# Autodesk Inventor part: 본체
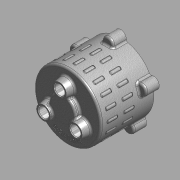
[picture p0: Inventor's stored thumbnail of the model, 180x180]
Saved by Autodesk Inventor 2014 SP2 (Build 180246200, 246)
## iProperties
Created: 2015-11
Part Number: 본체
Document SubType Name: 모델링
Designer: mdu
Material: 알루미늄 6061
Density: 2.71 g/cm^3
Appearance: 알루미늄 - 평지
Mass: 487.643 g
Surface Area: 696.803 cm^2
Volume: 179.942 cm^3
변환 표준: STEP AP214IS
파일 이름: C:\Users\SeoGD\Desktop\?쒗뿕\紐몄껜.stp
전처리기: Build: 253, Release: 2010 SP1 - Date: Wed 07/29/2009
전송 단위: 밀리미터
불확실성: 0.01
Author: mdu
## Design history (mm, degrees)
sketch "스케치2"
  geometry: C1 r 50 at (0, 0); 1 further point
  constraints: 1 centre point, 1 coincident
  dimensions: "d9" = 100 diameter of C1
extrude "돌출2" new body sketch "스케치2" distance "d10" = 80; taper "d11" = 0 deg
feature "쉘1" dims "d12" = 5
sketch "스케치3" dims "d13" = 55
  geometry: C1 r 7.5 at (0, 27.5); C2 r 12.5 at (0, 27.5); 2 further points
  constraints: 2 centre point, 2 coincident, 2 vertical alignment, 2 other
  dimensions: "d14" = 15 diameter of C1; "d15" = 25 diameter of C2
extrude "돌출3" join sketch "스케치3" distance "d16" = 12; taper "d17" = -10 deg
hole "구멍2" diameter "d20" = 15; stored, may be unused: countersink angle "d24" = 90 deg, drill point angle "d26" = 118 deg; dims "d18" = 10, "d19" = 10, "d21" = 6, "d22" = 4, "d23" = 2, "d25" = 15
chamfer "모따기1" distance "d27" = 1; stored, may be unused: second distance "d28" = 2, angle "d29" = 45 deg
sketch "스케치4"
  geometry: L1 (0, 0)-(0, 88); L2 (0, 70)-(13.16, 70); L3 (-45, 75)-(45, 75) reference; L4 (-50, 80)-(50, 80) reference; L5 (13.16, 70)-(14.5, 75); L6 (20, 80)-(20, 88); L7 (20, 88)-(0, 88); L8 (20, 80)-(14.5, 75)
  constraints: 12 end point, 3 point on line, 2 perpendicular, 1 vertical
  dimensions: "d34" = 40 diameter of L6 L1; "d35" = 105 deg angle of L5 L3; "d36" = 5 distance between parallel lines of L2 L3; "d37" = 8 distance between parallel lines of L7 L4; "d51" = 29 diameter of L5.end L1
revolve "회전1" sketch "스케치4" stored, may be unused: angle "d38" = 90 deg
hole "구멍3" diameter "d41" = 15; stored, may be unused: countersink angle "d45" = 90 deg, drill point angle "d47" = 0 deg; dims "d39" = 10, "d40" = 10, "d42" = 6, "d43" = 22, "d44" = 13, "d46" = 15
chamfer "모따기2" distance "d48" = 1; stored, may be unused: second distance "d49" = 2, angle "d50" = 45 deg
fillet "모깎기1" dims "d52" = 3
fillet "모깎기2" dims "d53" = 3, "d72" = 0.2
sketch "스케치5"
  geometry: A1 r 50 centre (0, 0) between (50, 0) and (-8.074, 49.344) reference; A2 r 8.5 centre (0, 52) between (8.074, 49.344) and (-8.074, 49.344); 1 further point
  constraints: 5 point on circle, 1 centre point, 1 horizontal alignment
  dimensions: "d54" = 90 deg dimension on point (0, 0) A2.centre A1.start; "d55" = 52 distance of A2.centre point (0, 0); "d56" = 17 diameter of A2
extrude "돌출4" join sketch "스케치5" distance "d57" = 20; taper "d58" = 0 deg
fillet "모깎기3" dims "d59" = 3
hole "구멍4" diameter "d62" = 4.134; stored, may be unused: countersink angle "d66" = 90 deg, drill point angle "d68" = 118 deg; dims "d60" = 10, "d61" = 10, "d63" = 12, "d64" = 22, "d65" = 13, "d67" = 15
sketch "스케치6"
  geometry: C1 r 47 at (0, 0) reference; C2 r 42.5 at (0, 0); 1 further point
  constraints: 1 centre point, 1 coincident, 1 other
  dimensions: "d73" = 85 diameter of C2
feature "엠보싱1" sketch "스케치6" dims "d74" = 0.5, "d75" = 0
node "작업 평면1"
sketch "스케치7"
  geometry: A1 r 50 centre (0, 0) between (5.144, 49.735) and (-5.144, 49.735) reference; A2 r 3 centre (0, 47.916) between (2.204, 49.951) and (-2.204, 49.951); 1 further point
  constraints: 4 point on circle, 1 centre point, 1 vertical alignment
  dimensions: "d77" = 3 radius of A2
extrude "돌출5" join sketch "스케치7" distance "d79" = 15; taper "d80" = 0 deg
fillet "모깎기4" dims "d81" = 1
fillet "모깎기5" dims "d82" = 1
node "솔리드1"
node "솔리드 본체"
node "곡면 본체"
pattern_circular "원형 패턴1" dims "d31" = 360 deg
pattern_circular "원형 패턴2" dims "d70" = 360 deg
pattern_circular "원형 패턴3" dims "d84" = 360 deg
pattern_linear "직사각형 패턴1" dims "d89" = 25
node "솔리드2"
